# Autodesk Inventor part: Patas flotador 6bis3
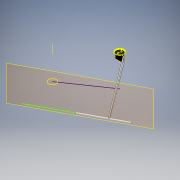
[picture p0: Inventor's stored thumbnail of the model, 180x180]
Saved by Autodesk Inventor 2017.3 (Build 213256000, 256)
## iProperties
Part Number: Patas flotador 6bis3
Material: Plástico ABS
Document SubType Name: Modeling
Designer: PABLO HERNANDEZ
Density: 1.06 g/cm^3
Appearance: Suave - Blanco
Mass: 4.28877 g
Surface Area: 39.5254 cm^2
Volume: 4.04601 cm^3
Author: M.RICO
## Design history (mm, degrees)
sketch "Boceto1"
  geometry: C1 r 16 at (0, 0); 1 further point
  constraints: 1 centre point, 1 coincident
  dimensions: "d0" = 32 diameter of C1
extrude "Extrusión1" new body sketch "Boceto1" distance "d1" = 1; taper "d2" = 0 deg; dims "d93" = 1, "d94" = 0
sketch "Boceto2"
  geometry: C1 r 16 at (0, 0); C2 r 15 at (0, 0); C3 r 14 at (0, 0); 1 further point
  constraints: 3 centre point, 1 coincident
  dimensions: "d3" = 1 radial gap between concentric circles of C1 C2; "d4" = 1 radial gap between concentric circles of C2 C3
extrude "Extrusión2" join sketch "Boceto2" distance "d5" = 3; taper "d6" = 0 deg
sketch "Boceto3"
  geometry: C1 r 15 at (0, 0); C2 r 14 at (0, 0); 1 further point
  constraints: 2 centre point, 1 coincident
  dimensions: "d7" = 1 radial gap between concentric circles of C1 C2; "d123" = 30 diameter of C1
extrude "Extrusión3" join sketch "Boceto3" distance "d8" = 2; taper "d9" = 0 deg
sketch "Boceto4"
  geometry: C1 r 16 at (0, 0); 1 further point
  constraints: 1 centre point, 1 coincident
extrude "Extrusión4" cut sketch "Boceto4" distance "d10" = 0.5; taper "d11" = 0 deg
sketch "Boceto7"
  geometry: L1 (1.5, -15.93)-(1.5, 15.93); L2 (-1.5, -15.93)-(-1.5, 15.93); A1 r 16 centre (0, 0) between (1.5, 15.93) and (-1.5, 15.93); A2 r 16 centre (0, 0) between (-1.5, -15.93) and (1.5, -15.93); 2 further points
  constraints: 4 end point, 4 point on circle, 2 centre point, 1 coincident
extrude "Extrusión7" join sketch "Boceto7" distance "d63" = 25; taper "d64" = 0 deg
fillet "Empalme2" dims "d95" = 3
fillet "Empalme3" dims "d96" = 0.5
sketch "Boceto13"
  geometry: C1 r 1.2 at (-6, 0) reference; C2 r 1.75 at (-6, 0); C3 r 1.2 at (6, 0) reference; C4 r 1.75 at (6, 0); 1 further point
  constraints: 2 centre point, 2 coincident
  dimensions: "d118" = 3.5 diameter of C2; "d119" = 3.5 diameter of C4
extrude "Extrusión10" join sketch "Boceto13" distance "d120" = 3; taper "d121" = 0 deg
fillet "Empalme4" dims "d122" = 1
sketch "Boceto14"
  geometry: 1 further point
sketch "Boceto15"
  geometry: C1 r 1.2 at (6, 0) reference; C2 r 2.5 at (6, 0); C3 r 1.2 at (-6, 0) reference; C4 r 2.5 at (-6, 0); 1 further point
  constraints: 2 centre point, 2 coincident
  dimensions: "d124" = 5 diameter of C2; "d125" = 5 diameter of C4
extrude "Extrusión11" cut sketch "Boceto15" distance "d126" = 10; taper "d127" = 0 deg
hole "Agujero7" diameter "d151" = 2.4; stored, may be unused: countersink angle "d155" = 90 deg, drill point angle "d157" = 118 deg; dims "d149" = 10, "d150" = 10, "d152" = 6, "d153" = 4, "d154" = 2, "d156" = 8
hole "Agujero8" diameter "d160" = 2.4; stored, may be unused: countersink angle "d164" = 90 deg, drill point angle "d166" = 118 deg; dims "d158" = 10, "d159" = 10, "d161" = 6, "d162" = 4, "d163" = 2, "d165" = 8
node "Eje de trabajo1"
feature "Desplazar cuerpo1"
feature "Compuesta1"
feature "Desplazar cuerpo2"
node "Eje de trabajo2"
feature "Desplazar cuerpo3"
node "Plano de trabajo6"
sketch "Boceto27"
  geometry: L1 (0, 0)-(-149.324, -102.291); L2 (-134.431, -229.557)-(132.044, -87.232); C1 r 14 at (-149.324, -102.291) reference
  constraints: 4 end point
node "Plano de trabajo7"
node "Plano de trabajo8"
sketch "Boceto28"
  geometry: C1 r 2 at (0, 0); 1 further point
  constraints: 1 centre point
  dimensions: "d177" = 4 diameter of C1
extrude "Extrusión14" join sketch "Boceto28" stored distance "d178" = 10; taper "d179" = 0 deg
sketch "Boceto29"
  geometry: L1 (-0.28, 0)-(0, 0) reference; L2 (0, 0)-(-102.216, -91.987); L3 (-0.28, 23.165)-(-0.28, 0) reference; L4 (0, 23.165)-(0, 0) reference; L5 (0, 0)-(0, 23.165); L6 (0, 23.165)-(-105.015, -89.134); C1 r 2 at (-103.554, -90.5) reference; A1 r 2 centre (-103.554, -90.5) between (-102.216, -91.987) and (-105.015, -89.134) reference; 1 further point
  constraints: 6 end point, 2 point on circle, 2 tangent, 1 collinear
extrude "Extrusión15" join sketch "Boceto29" stored distance "d180" = 10; taper "d181" = 0 deg
node "Plano de trabajo9"
sketch "Boceto30"
  geometry: L1 (1.356, 23.165)-(1.356, 0) reference; L2 (1.356, 0)-(-130.469, -92.139); L3 (1.356, 0)-(1.356, 23.165); L4 (1.356, 23.165)-(-132.897, -88.965); A1 r 2 centre (-131.615, -90.5) between (-130.469, -92.139) and (-132.897, -88.965) reference; A2 r 2 centre (-131.615, -90.5) between (-132.897, -88.965) and (-130.469, -92.139); 1 further point
  constraints: 6 end point, 4 point on circle, 2 tangent, 1 centre point, 1 coincident, 1 vertical
extrude "Extrusión16" join sketch "Boceto30" distance "d182" = 3; taper "d183" = 0 deg
node "Plano de trabajo10"
sketch "Boceto31"
  geometry: L1 (-7.175, -6.405)-(170.651, -6.405); L2 (170.651, -6.405)-(170.651, 129.955); L3 (170.651, 129.955)-(-7.175, 129.955); L4 (-7.175, 129.955)-(-7.175, -6.405); 1 further point
  constraints: 8 end point, 2 parallel, 1 horizontal, 1 perpendicular
extrude "Extrusión17" cut sketch "Boceto31" distance "d185" = 150; taper "d186" = 0 deg
sketch "Boceto32"
  geometry: C1 r 1 at (0, 0); 1 further point
  constraints: 1 centre point
  dimensions: "d187" = 2 diameter of C1
extrude "Extrusión18" cut sketch "Boceto32" distance "d188" = 6; taper "d189" = 0 deg
sketch "Boceto33"
  geometry: L1 (31.859, 0)-(0, 0) reference; L2 (0, -3)-(31.859, -3) reference; L3 (31.859, 0)-(0, 0); L4 (0, 0)-(0, -3); L5 (0, -3)-(31.859, -3); L6 (31.859, -3)-(31.859, 0); 1 further point
  constraints: 8 end point, 2 parallel, 1 horizontal, 1 perpendicular
extrude "Extrusión19" cut sketch "Boceto33" distance "d191" = 24; taper "d192" = 0 deg
node "Plano de trabajo11"
node "Sólido1"
node "Sup1"
other parameters: "sa_0" = 4, "d167" = 90 deg, "d168" = -149.324, "d169" = -102.291, "d170" = 0, "d171" = 9.86699, "d184" = 147, "d193" = 90 deg
